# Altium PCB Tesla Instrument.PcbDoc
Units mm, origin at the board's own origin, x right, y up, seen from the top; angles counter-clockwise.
Board outline 84.07 x 76.45 mm, 2 copper layers (Top Layer, Bottom Layer); 15 components, 16 nets, 95 pads, 0 vias.
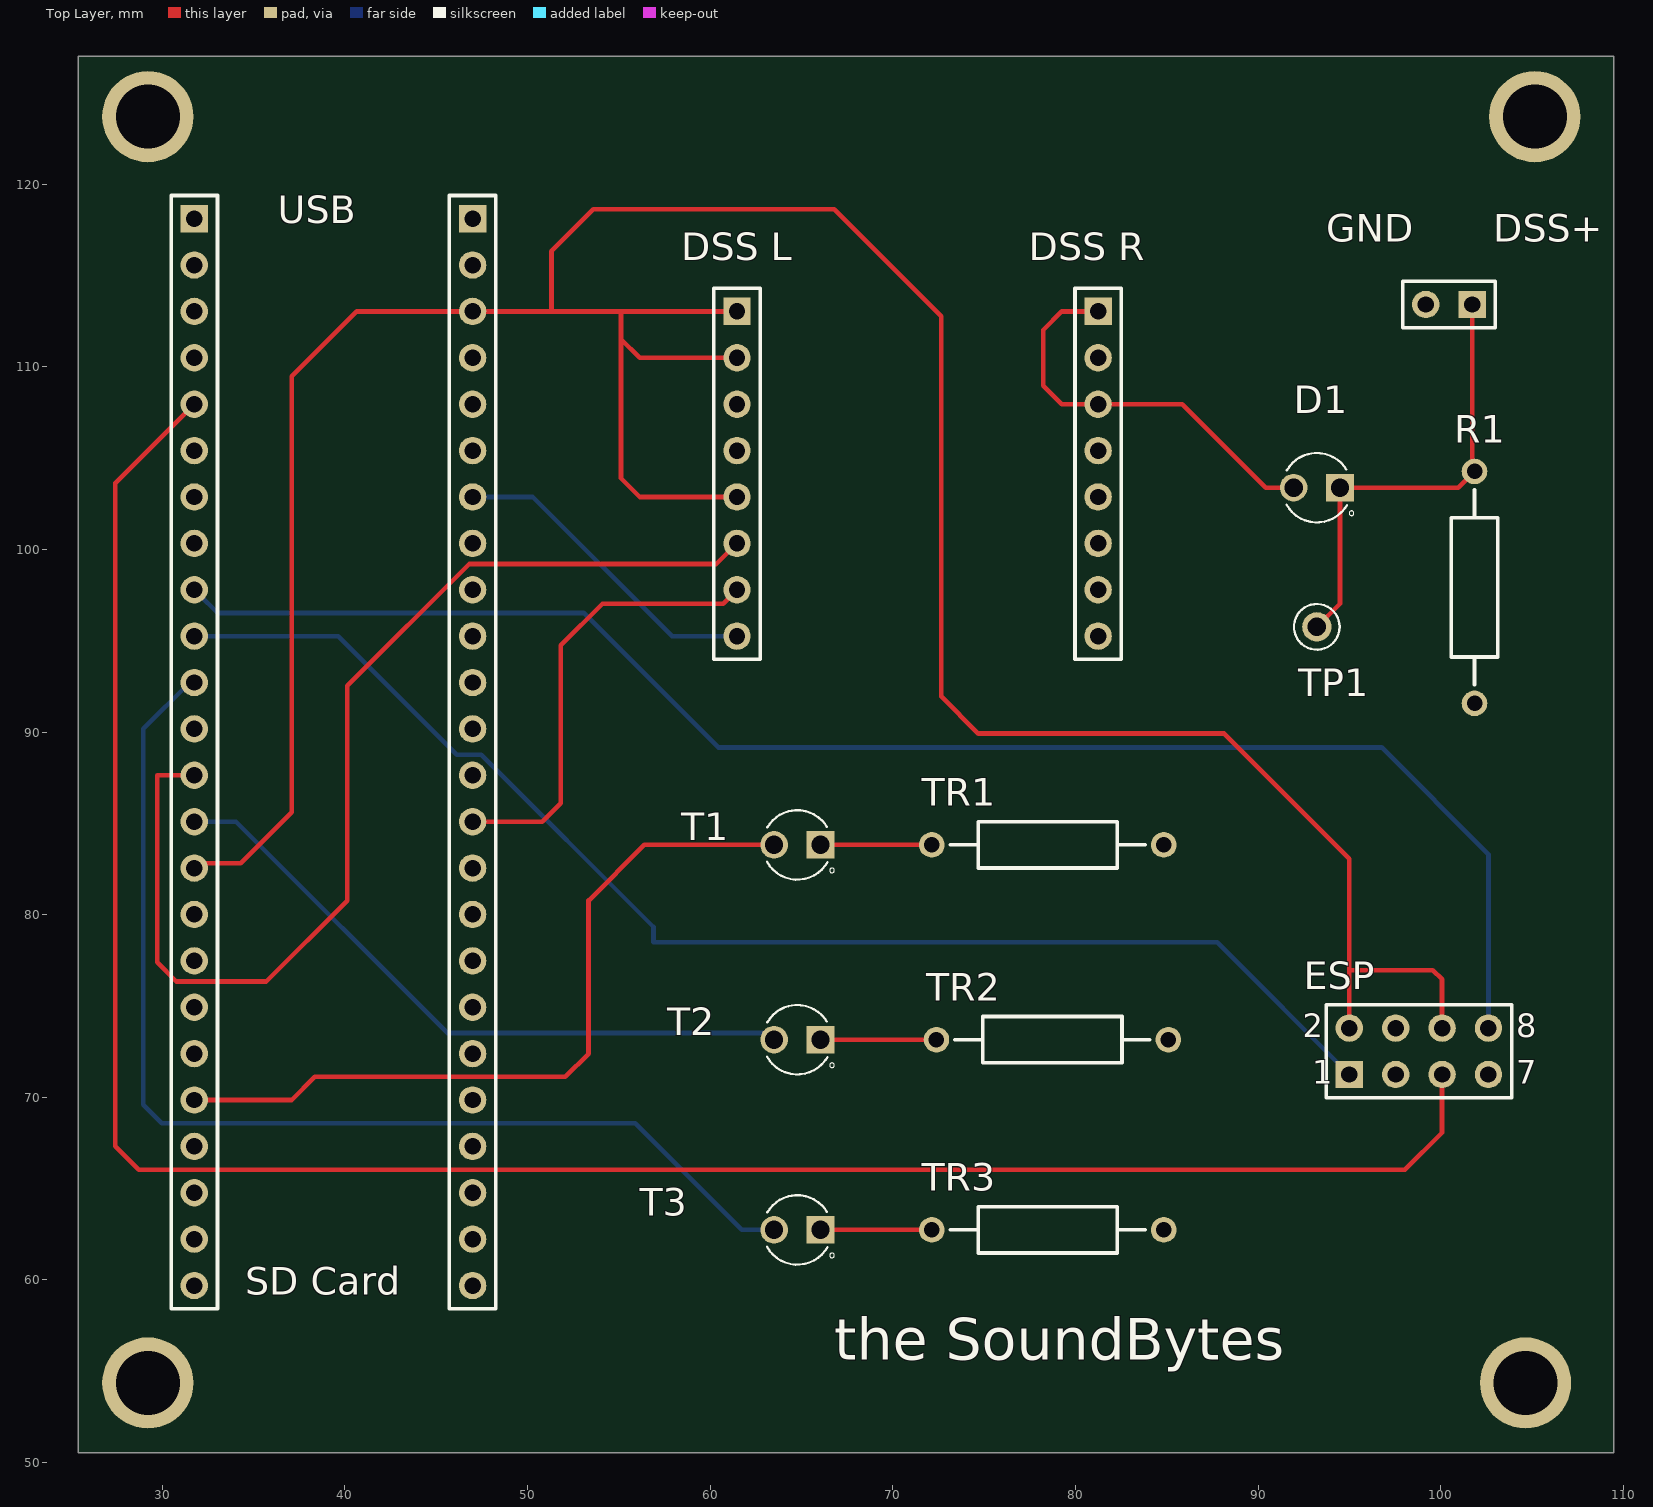
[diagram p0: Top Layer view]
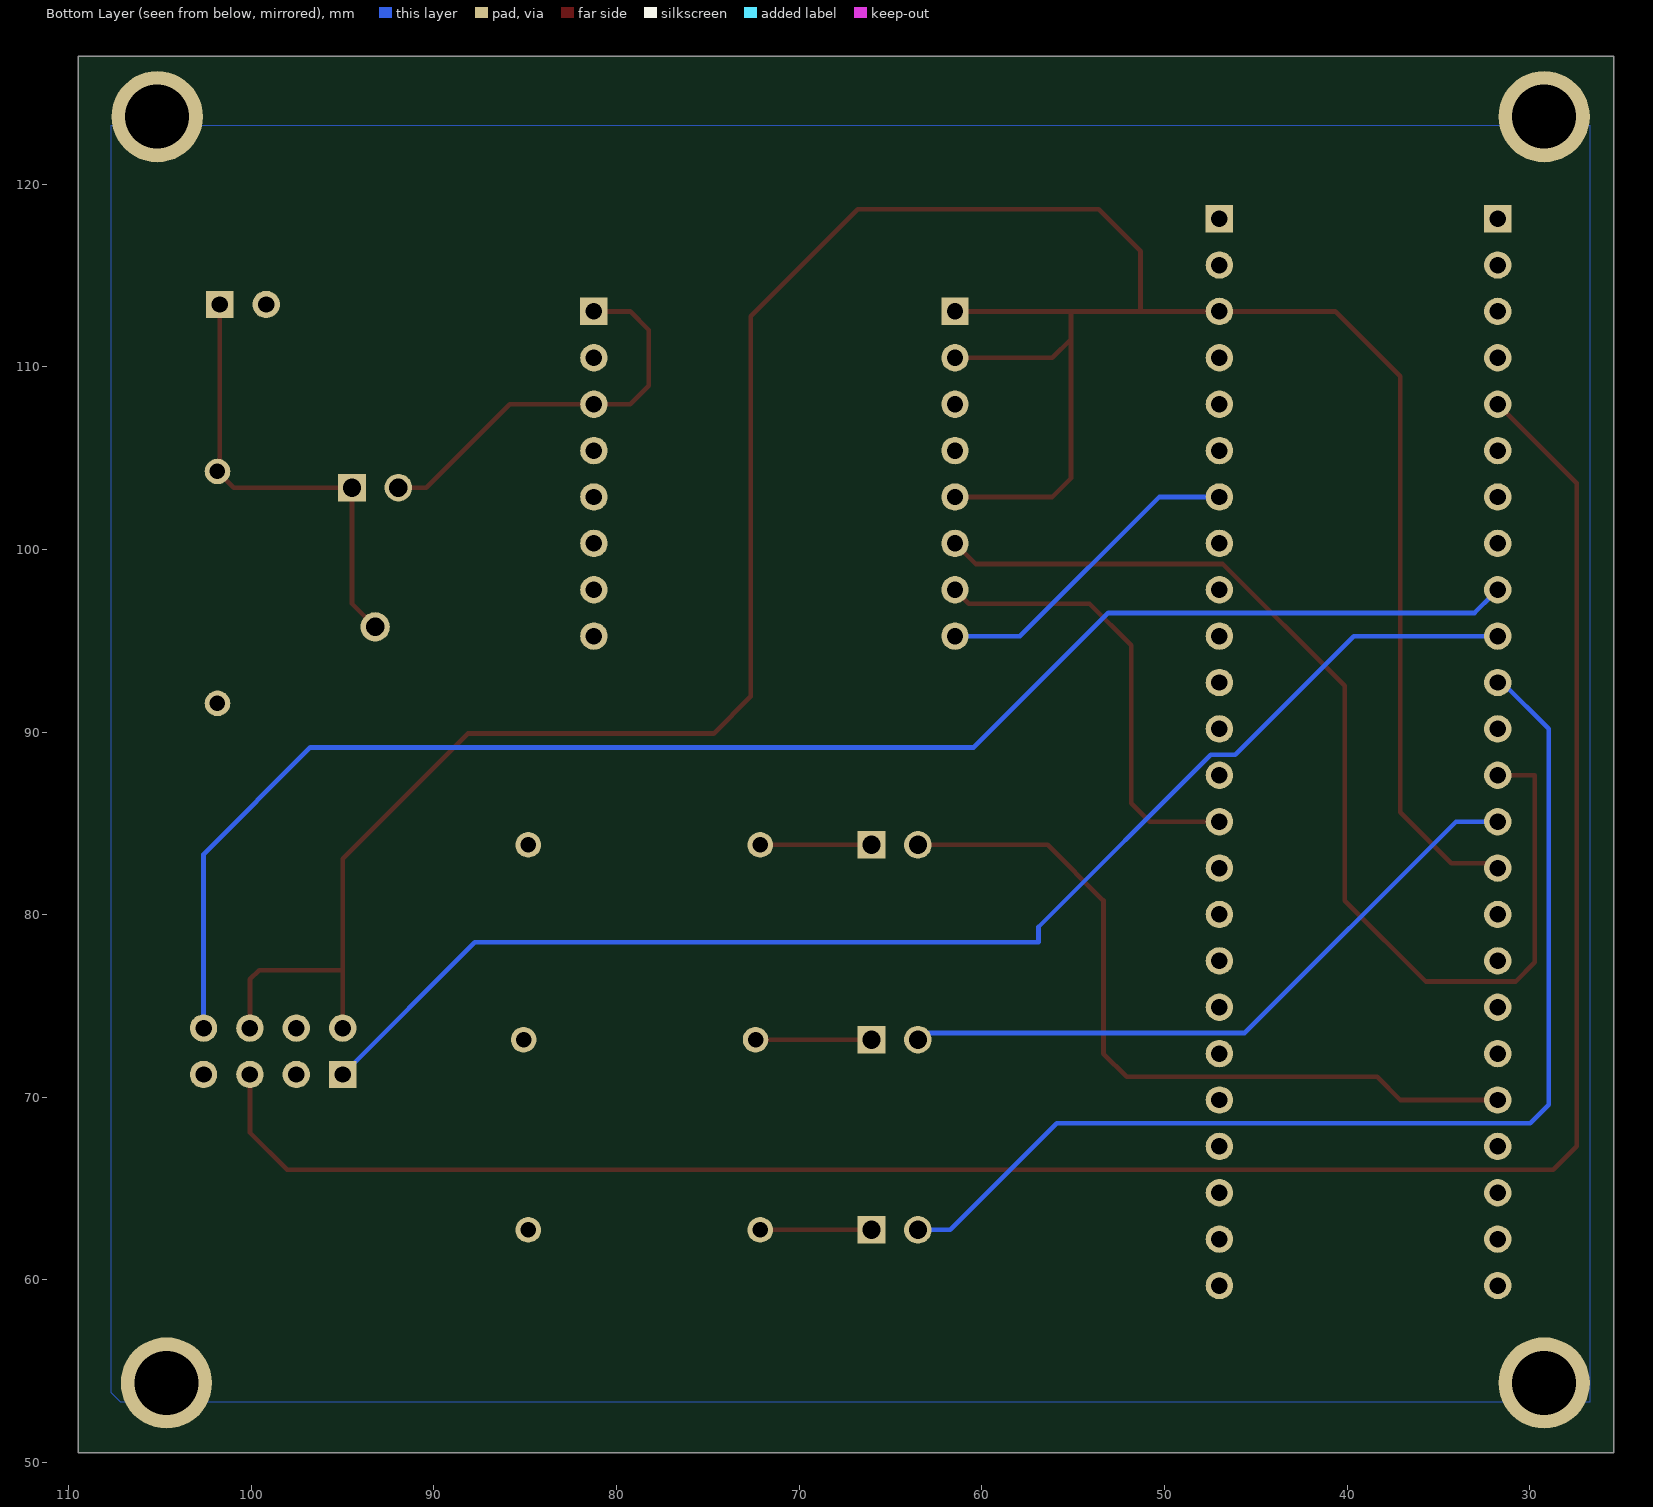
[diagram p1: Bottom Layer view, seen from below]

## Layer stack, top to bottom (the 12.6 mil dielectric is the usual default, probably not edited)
Top Solder: solder mask 0.0102, Solder Resist, Dk 3.5
Top Layer: signal copper 0.0356
Dielectric 1: dielectric 0.32, FR-4, Dk 4.8
Bottom Layer: signal copper 0.0356
Bottom Solder: solder mask 0.0102, Solder Resist, Dk 3.5

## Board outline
25.4,50.546 109.474,50.546 109.474,127 25.4,127

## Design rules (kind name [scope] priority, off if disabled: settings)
Clearance [All] p1: gap=0.254
PolygonConnect [All] p1: connectstyle=Relief reliefconductorwidth=0.254 reliefentries=4 polygonreliefangle="90 Angle" airgapwidth=0.254
RoutingVias [All] p1: holewidth=0.711 width=1.27 viastyle="Through Hole" minholewidth=0.711 minwidth=1.27 maxholewidth=0.711 maxwidth=1.27
SolderMaskExpansion [All] p1: expansion=0.102
Width [All] p1: maxlimit=0.254 minlimit=0.254 preferedwidth=0.254
30 further rules are at their usual default settings.

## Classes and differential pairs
component class "Tesla Instrument": D1 "DSS L" "DSS R" ESP R1 T1 T2 T3 TP1 TR1 TR2 TR3 ""

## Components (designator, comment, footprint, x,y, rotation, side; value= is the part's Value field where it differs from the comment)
D1 "LTL-1CHYE" LED_LTL-1CHYE_LTL-1CHYE(Primary) 93.218,103.378 r180 top
"DSS L" "Header 8" HDR1X8 61.468,113.03 r270 top
"DSS R" "Header 8" HDR1X8 81.243,113.03 r270 top
ESP "Header 4X2" HDR2X4 94.996,71.247 r0 top
P1 "Header 2" HDR1X2 101.727,113.411 r180 top
R1 "Res Semi" AXIAL-0.5 101.854,97.917 r90 top
T1 "LTL-1CHYE" LED_LTL-1CHYE_LTL-1CHYE(Primary) 64.77,83.82 r180 top
T2 "LTL-1CHYE" LED_LTL-1CHYE_LTL-1CHYE(Primary) 64.77,73.152 r180 top
T3 "LTL-1CHYE" LED_LTL-1CHYE_LTL-1CHYE(Primary) 64.77,62.738 r180 top
"Teensy L" "Header 24" HDR1X24 31.75,118.11 r270 top
"Teensy R" "Header 24" HDR1X24 46.99,118.11 r270 top
TP1 "" TPCW51D250H460P 93.218,95.758 r0 top
TR1 "" AXIAL-0.5 78.486,83.82 r180 top
TR2 "" AXIAL-0.5 78.74,73.152 r180 top
TR3 "" AXIAL-0.5 78.486,62.738 r180 top

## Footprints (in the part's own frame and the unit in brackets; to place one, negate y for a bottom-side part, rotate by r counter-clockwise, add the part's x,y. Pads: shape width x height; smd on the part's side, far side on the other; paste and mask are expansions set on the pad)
AXIAL-0.5 [mm] "Axial Device, Thru-Hole; 2 Leads; 0.5 in Pin Spacing"
  round 1.4 hole 0.85: 1(-6.35,0) 2(6.35,0)
  silkscreen extent -5.33,-1.27 5.33,1.27
HDR1X2 [mm] "Connector; Header; 2 Position"
  rect 1.5x1.5 hole 0.9: 1(0,0)
  round 1.5 hole 0.9: 2(2.54,0)
  silkscreen extent -1.27,-1.27 3.81,1.27
HDR1X8 [mm] "Connector; Header; 8 Position"
  rect 1.5x1.5 hole 0.9: 1(0,0)
  round 1.5 hole 0.9: 2(2.54,0) 3(5.08,0) 4(7.62,0) 5(10.16,0) 6(12.7,0) 7(15.24,0) 8(17.78,0)
  silkscreen extent -1.27,-1.27 19.05,1.27
HDR1X24 [mm] "Connector; Header; 24 Position"
  rect 1.5x1.5 hole 0.9: 1(0,0)
  round 1.5 hole 0.9: 2(2.54,0) 3(5.08,0) 4(7.62,0) 5(10.16,0) 6(12.7,0) 7(15.24,0) 8(17.78,0) 9(20.32,0) 10(22.86,0) 11(25.4,0) 12(27.94,0) 13(30.48,0) 14(33.02,0) 15(35.56,0) 16(38.1,0) 17(40.64,0) 18(43.18,0) 19(45.72,0) 20(48.26,0) 21(50.8,0) 22(53.34,0) 23(55.88,0) 24(58.42,0)
  silkscreen extent -1.27,-1.27 59.69,1.27
HDR2X4 [mm] "Connector; Header; 4x2 Position"
  rect 1.5x1.5 hole 0.9: 1(0,0)
  round 1.5 hole 0.9: 2(0,2.54) 3(2.54,0) 4(2.54,2.54) 5(5.08,0) 6(5.08,2.54) 7(7.62,0) 8(7.62,2.54)
  silkscreen extent -1.27,-1.27 8.89,3.81
LED_LTL-1CHYE_LTL-1CHYE(Primary) [mm]
  round 1.508 hole 1: A(1.27,0)
  rect 1.508x1.508 hole 1: C(-1.27,0)
  silkscreen extent -2.03,-1.9 1.66,1.9
TPCW51D250H460P [mm]
  round 1.6 hole 1.02: 1(0,0)
  silkscreen extent -1.25,-1.25 1.25,1.25

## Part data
D1 T1 T2 T3: "Yellow 3.1 mm 45° Tinted Clear 40 mcd 2.1 V LED Through Hole"
"DSS L" "DSS R": "Header, 8-Pin"
ESP: "Header, 4-Pin, Dual row"
P1: "Header, 2-Pin"
R1: "Semiconductor Resistor"
"Teensy L" "Teensy R": "Header, 24-Pin"
TP1: library part 5003, "Test Point; Orange; Thru-Hole; Snap-Fit; SilverPlate; 0.040 in. Dia.; 0.300 In."
TR1 TR2 TR3: library part "Res Semi", "Semiconductor Resistor"

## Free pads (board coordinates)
  round 5 hole 3.5: 2(29.21,123.698) 3(105.156,123.698) 4(104.648,54.356) 5(29.21,54.356)

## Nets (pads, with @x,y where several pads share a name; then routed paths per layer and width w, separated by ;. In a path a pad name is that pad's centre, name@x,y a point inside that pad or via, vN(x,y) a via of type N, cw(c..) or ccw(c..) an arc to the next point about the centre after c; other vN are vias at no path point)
3V3: "DSS L.1" "DSS L.2" "DSS L.5" "Teensy L.15" "Teensy R.3" ESP.2 ESP.6 | length 171.1
  Top Layer w0.254: 31.75,82.55 32.004,82.804 34.29,82.804 37.084,85.598 37.084,109.474 40.64,113.03 46.99,113.03 51.308,113.03 ; 61.468,102.87 56.134,102.87 55.118,103.886 55.118,111.506 ; 61.468,110.49 56.134,110.49 55.118,111.506 ; 61.468,113.03 55.118,113.03 ; ESP.2 94.996,76.962 ; ESP.6 100.076,76.454 99.568,76.962 94.996,76.962 ; 51.308,113.03 55.118,113.03 ; 51.308,113.03 51.308,116.332 53.594,118.618 66.802,118.618 72.644,112.776 72.644,91.948 74.676,89.916 88.138,89.916 94.996,83.058 94.996,76.962 ; 55.118,111.506 55.118,113.03
24: "Teensy L.14" T2.A | length 36.7
  Bottom Layer w0.254: 31.75,85.09 34.036,85.09 45.605,73.521 63.131,73.521 T2.A
28: "Teensy L.20" T1.A | length 42.4
  Top Layer w0.254: 31.75,69.85 37.084,69.85 38.354,71.12 52.07,71.12 53.34,72.39 53.34,80.772 56.388,83.82 T1.A
CS1: "DSS L.8" "Teensy R.7" | length 17.6
  Bottom Layer w0.254: 46.99,102.87 50.292,102.87 57.912,95.25 61.468,95.25
GND: "DSS L.3" "DSS L.4" "Teensy L.1" "Teensy R.2" "Teensy R.15" ESP.7 P1.2 R1.1 TR1.1 TR2.1 TR3.1
NetD1_A: "DSS R.1" "DSS R.3" D1.A | length 22.5
  Top Layer w0.254: 81.243,113.03 79.248,113.03 78.232,112.014 78.232,108.966 79.248,107.95 81.243,107.95 85.852,107.95 90.424,103.378 D1.A
NetD1_C: D1.C P1.1 R1.2 TP1.1 | length 25.1
  Top Layer w0.254: TP1.1 94.488,97.028 D1.C 100.965,103.378 R1.2 101.727,104.394 P1.1
NetT1_C: T1.C TR1.2 | length 6.1
  Top Layer w0.254: T1.C TR1.2
NetT2_C: T2.C TR2.2 | length 6.3
  Top Layer w0.254: T2.C TR2.2
NetT3_A: "Teensy L.11" T3.A | length 61.8
  Bottom Layer w0.254: 31.75,92.71 31.496,92.71 28.956,90.17 28.956,69.596 29.972,68.58 55.896,68.58 61.738,62.738 T3.A
NetT3_C: T3.C TR3.2 | length 6.1
  Top Layer w0.254: T3.C TR3.2
PIN3: "Teensy L.5" ESP.5 | length 119.6
  Top Layer w0.254: 31.75,107.95 27.432,103.632 27.432,67.31 28.702,66.04 98.044,66.04 100.076,68.072 ESP.5
PIN7: "Teensy L.9" ESP.8 | length 86.9
  Bottom Layer w0.254: 31.75,97.79 32.004,98.044 32.004,97.536 33.02,96.52 53.086,96.52 60.452,89.154 96.774,89.154 102.616,83.312 ESP.8
PIN8: "Teensy L.10" ESP.1 | length 73.7
  Bottom Layer w0.254: 31.75,95.25 39.624,95.25 46.113,88.761 47.458,88.761 56.896,79.323 56.896,78.486 87.757,78.486 ESP.1
SCK: "DSS L.7" "Teensy R.14" | length 24.8
  Top Layer w0.254: 46.99,85.09 50.8,85.09 51.816,86.106 51.816,94.742 54.102,97.028 60.706,97.028 61.468,97.79
SDA: "DSS L.6" "Teensy L.13" | length 61.3
  Top Layer w0.254: 31.75,87.63 29.718,87.63 29.718,77.395 30.774,76.339 35.699,76.339 40.132,80.772 40.132,92.531 46.8,99.199 60.337,99.199 61.468,100.33
pads on no net: "DSS R.2" "DSS R.4" "DSS R.5" "DSS R.6" "DSS R.7" "DSS R.8" "Teensy L.2" "Teensy L.3" "Teensy L.4" "Teensy L.6" "Teensy L.7" "Teensy L.8" "Teensy L.12" "Teensy L.16" "Teensy L.17" "Teensy L.18" "Teensy L.19" "Teensy L.21" "Teensy L.22" "Teensy L.23" "Teensy L.24" "Teensy R.1" "Teensy R.4" "Teensy R.5" "Teensy R.6" "Teensy R.8" "Teensy R.9" "Teensy R.10" "Teensy R.11" "Teensy R.12" "Teensy R.13" "Teensy R.16" "Teensy R.17" "Teensy R.18" "Teensy R.19" "Teensy R.20" "Teensy R.21" "Teensy R.22" "Teensy R.23" "Teensy R.24" ESP.3 ESP.4

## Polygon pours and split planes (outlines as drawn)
GND on Bottom Layer "GND" (hatched 90Degree grid 0.508 track 0.203, shelved, pour order 0): 26.67,123.19 107.696,123.19 107.696,53.848 107.188,53.34 26.67,53.34 26.67,123.19

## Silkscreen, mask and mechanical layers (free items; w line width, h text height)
Top Overlay:
  text "USB" at 36.322,117.856 h1.52
  text "GND" at 93.726,116.84 h1.52
  text "DSS+" at 102.87,116.84 h1.52
  text "SD Card" at 34.544,59.182 h1.52
  text "the SoundBytes" at 66.802,55.626 h2.29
